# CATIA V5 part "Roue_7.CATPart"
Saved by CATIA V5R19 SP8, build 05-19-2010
Part number: Roue_7
Nomenclature: 70_R7
Bounding box of the stored display mesh (mm): x -12.994 to 12.994, y -13 to 13, z 0 to 1.5
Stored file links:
  C:\Users\rphgr\Desktop\0_Tapis_TC520B_vitesse\Roue_7.CATPart
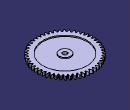
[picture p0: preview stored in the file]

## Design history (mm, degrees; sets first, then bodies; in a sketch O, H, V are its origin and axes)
External parameters (linked from other documents)
  External.Module = 0.5 mm
  External.Z = 50
  External.DiamPrimitif = 25 mm {= External.Module *External.Z}
  External.AnglePression = 20 deg
  External.x = 0
  External.DeportDenture = 0 mm {= External.x *External.Module}
  External.DiamBase = 23.4923 mm {= External.DiamPrimitif *cos(External.AnglePression )}
  External.DiamPied = 23.75 mm {= External.DiamPrimitif -2.5*External.Module +2*External.DeportDenture}
  External.DiamTete = 26 mm {= External.DiamPrimitif +2*External.Module +2*External.DeportDenture}
  External.PhiPrimitif = 0.854 deg {= atan((sin(External.ThetaPrimitif*1rad)-External.ThetaPrimitif*cos(External.ThetaPrimitif*1rad))/(cos(External.ThetaPrimitif*1rad)+External.ThetaPrimitif*sin(External.ThetaPrimitif*1rad)))}
  External.PhiTete = 1.7996 deg {= atan((sin(External.ThetaTete*1rad)-External.ThetaTete*cos(External.ThetaTete*1rad))/(cos(External.ThetaTete*1rad)+External.ThetaTete*sin(External.ThetaTete*1rad)))}
  External.PhiSymetrie = 1.8 deg {= 180*1 deg/(2*External.Z )}
  External.CongePied = 0.19 mm {= 0.38*External.Module}
  External.AlphaCopie = 7.2 deg {= 360*1 deg/External.Z}
  External.AlphaSymetrieCopie = 3.6 deg {= External.AlphaCopie /2}
  External.CoeffQualiteEngrenage = 7
  External.LargeurDenture = 1.5 mm
  External.ThetaPrimitif = 0.36397 {= sqrt(abs((External.DiamPrimitif*External.DiamPrimitif)/(External.DiamBase *External.DiamBase )-1))}
  External.ThetaTete = 0.47422 {= sqrt(abs((External.DiamTete*External.DiamTete)/(External.DiamBase *External.DiamBase )-1) )}
  External.Di = 24.2462 mm {= (External.DiamBase +External.DiamPrimitif )/2}
  External.Thetai = 0.255358 {= sqrt(abs((External.Di*External.Di)/(External.DiamBase*External.DiamBase)-1))}
  External.Phii = 0.3061 deg {= atan((sin(External.Thetai*1rad)-External.Thetai*cos(External.Thetai*1rad))/(cos(External.Thetai*1rad)+External.Thetai*sin(External.Thetai*1rad)))}
  External.Dj = 25.5 mm {= (External.DiamTete+External.DiamPrimitif)/2}
  External.Thetaj = 0.422169 {= sqrt(abs((External.Dj*External.Dj)/(External.DiamBase*External.DiamBase)-1))}
  External.Phij = 1.3005 deg {= atan((sin(External.Thetaj*1rad)-External.Thetaj*cos(External.Thetaj*1rad))/(cos(External.Thetaj*1rad)+External.Thetaj*sin(External.Thetaj*1rad)))}
  External.Dk = 23.8692 mm {= (External.Di+External.DiamBase)/2}
  External.Thetak = 0.179851 {= sqrt(abs((External.Dk*External.Dk)/(External.DiamBase*External.DiamBase)-1))}
  External.Phik = 0.109 deg {= atan((sin(External.Thetak*1rad)-External.Thetak*cos(External.Thetak*1rad))/(cos(External.Thetak*1rad)+External.Thetak*sin(External.Thetak*1rad)))}
  External.Dl = 24.6231 mm {= (External.DiamPrimitif+External.Di)/2}
  External.Thetal = 0.31398 {= sqrt(abs((External.Dl*External.Dl)/(External.DiamBase*External.DiamBase)-1))}
  External.Phil = 0.5585 deg {= atan((sin(External.Thetal*1rad)-External.Thetal*cos(External.Thetal*1rad))/(cos(External.Thetal*1rad)+External.Thetal*sin(External.Thetal*1rad)))}
  External.Dm = 25.25 mm {= (External.Dj+External.DiamPrimitif)/2}
  External.Thetam = 0.394001 {= sqrt(abs((External.Dm*External.Dm)/(External.DiamBase*External.DiamBase)-1))}
  External.Phim = 1.0701 deg {= atan((sin(External.Thetam*1rad)-External.Thetam*cos(External.Thetam*1rad))/(cos(External.Thetam*1rad)+External.Thetam*sin(External.Thetam*1rad)))}
  External.Dn = 25.75 mm {= (External.DiamTete+External.Dj)/2}
  External.Thetan = 0.448823 {= sqrt(abs((External.Dn*External.Dn)/(External.DiamBase*External.DiamBase)-1))}
  External.Phin = 1.544 deg {= atan((sin(External.Thetan*1rad)-External.Thetan*cos(External.Thetan*1rad))/(cos(External.Thetan*1rad)+External.Thetan*sin(External.Thetan*1rad)))}
  External.DiametreAlesage = 2 mm
Body1 (main body)
  Sketch1 on xy-plane, origin (0, 0, 0), H (1, 0, 0), V (0, 1, 0)
    construction circle A1 centre (0, 0) radius 12.5
    construction circle A2 centre (0, 0) radius 11.7462
    construction circle A3 centre (0, 0) radius 11.875
    construction circle A4 centre (0, 0) radius 13
    point P1 (11.7462, 0)
    construction line L1 (11.7462, 0) -> (0, 0)
    point P2 (12.4986, 0.1863)
    construction line L2 (12.4986, 0.1863) -> (0, 0)
    point P3 (12.9936, 0.4082)
    construction line L3 (12.9936, 0.4082) -> (0, 0)
    construction line L4 (11.7462, 0) -> (11.7462, 3.9367)
    point P4 (11.7462, 0)
    point P6 (10.9937, 0.1863)
    construction line L5 (12.9936, 0.4082) -> (12.4986, 0.1863)
    point P7 (12.7461, 0.2973)
    point P8 (10.7462, 0.2973)
    spline S1 through (10.7462, 0.2973) (10.9937, 0.1863) (11.7462, 0) (11.9346, 0.0227) (12.1229, 0.0648) (12.311, 0.12) (12.4986, 0.1863) (12.6228, 0.2358) (12.7467, 0.2894) (12.8703, 0.3469) (12.9936, 0.4082)
    construction line L6 (0, 0) -> (5.2687, 0.2442)
    spline S2 through (10.7276, 0.6981) (10.9638, 0.8315) (11.6958, 1.0866) (11.8855, 1.0814) (12.0769, 1.057) (12.2693, 1.0194) (12.4623, 0.9707) (12.5905, 0.9329) (12.7188, 0.891) (12.8472, 0.8452) (12.9756, 0.7955)
    arc A5 centre (12.0641, -0.1449) radius 0.19 from (12.0229, 0.0405) to (11.8741, -0.1427) ccw
    point P11 (11.8741, -0.1427)
    arc A6 centre (0, 0) radius 13 from (12.9936, 0.4082) to (12.9756, 0.7955) ccw
    point P13 (12.9756, 0.7955)
    arc A7 centre (11.999, 1.2603) radius 0.19 from (11.81, 1.2405) to (11.9751, 1.0719) ccw
    point P15 (11.81, 1.2405)
    construction line L7 (0, 0) -> (4.2577, 0.4666)
    construction line L8 (0, 0) -> (5.1252, -0.0846)
    point P19 (11.8043, 1.2936)
    arc A8 centre (0, 0) radius 11.875 from (11.81, 1.2405) to (11.8043, 1.2936) ccw
    point P20 (11.8734, -0.1961)
    arc A9 centre (0, 0) radius 11.875 from (11.8734, -0.1961) to (11.8741, -0.1427) ccw
    line L9 (11.8043, 1.2936) -> (0, 0)
    line L10 (11.8734, -0.1961) -> (0, 0)
    construction circle A10 centre (0, 0) radius 12.1231
    construction line L11 (0, 0) -> (2.5698, 0.0137)
    point P22 (12.1229, 0.0648)
    construction circle A11 centre (0, 0) radius 12.75
    construction line L12 (0, 0) -> (4.018, 0.0912)
    point P24 (12.7467, 0.2894)
    point P25 (12.7467, 0.2894)
    point P26 (12.7188, 0.891)
    point P27 (12.0769, 1.057)
    construction circle A12 centre (0, 0) radius 11.9346
    construction line L13 (0, 0) -> (48.2618, 0.0918)
    point P29 (11.8855, 1.0814)
    construction line L14 (0, 0) -> (63.9099, 2.9624)
    point P31 (11.9346, 0.0227)
    construction circle A13 centre (0, 0) radius 12.3115
    construction line L15 (0, 0) -> (57.3607, 0.5591)
    point P33 (12.311, 0.12)
    point P34 (12.2693, 1.0194)
    construction circle A14 centre (0, 0) radius 12.625
    construction line L16 (0, 0) -> (65.6993, 1.2272)
    point P36 (12.6228, 0.2358)
    point P37 (12.5905, 0.9329)
    construction circle A15 centre (0, 0) radius 12.875
    axis line L17 (0, 0) -> (59.3294, 1.5992)
    point P39 (12.8472, 0.8452)
    point P40 (12.8703, 0.3469)
    point P42 (10.7462, 0.2973)
    point P43 (10.9937, 0.1863)
    point P44 (11.7462, 0)
    point P45 (12.4986, 0.1863)
    point P46 (12.9936, 0.4082)
    point P47 (12.9756, 0.7955)
    point P48 (10.7276, 0.6981)
    point P49 (12.4623, 0.9707)
    point P50 (11.6958, 1.0866)
    point P51 (10.9638, 0.8315)
    point P52 (12.1229, 0.0648)
    point P53 (12.7467, 0.2894)
    point P54 (12.0769, 1.057)
    point P55 (12.7188, 0.891)
    point P56 (11.9346, 0.0227)
    point P57 (11.8855, 1.0814)
    point P58 (12.311, 0.12)
    point P59 (12.2693, 1.0194)
    point P60 (12.6228, 0.2358)
    point P61 (12.5905, 0.9329)
    point P62 (12.8703, 0.3469)
    point P63 (12.8472, 0.8452)
    radius A1 = 12.5 {= External.DiamPrimitif /2}
    radius A2 = 11.7462 {= External.DiamBase /2}
    radius A3 = 11.875 {= External.DiamPied /2}
    radius A4 = 13 {= External.DiamTete /2}
    angle L2 L1 = 0.854 {= External.PhiPrimitif}
    angle L3 L1 = 1.7996 {= External.PhiTete}
    angle L4 L1 = 90
    radius A5 = 0.19 {= External.CongePied}
    radius A7 = 0.19 {= External.CongePied}
    angle L7 L6 = 3.6 {= External.AlphaSymetrieCopie}
    angle L2 L6 = 1.8 {= External.PhiSymetrie}
    radius A10 = 12.1231 {= External.Di /2}
    angle L11 L1 = 0.3061 {= External.Phii}
    radius A11 = 12.75 {= External.Dj /2}
    angle L12 L1 = 1.3005 {= External.Phij}
    radius A12 = 11.9346 {= External.Dk/2}
    angle L13 L1 = 0.109 {= External.Phik}
    angle L14 L2 = 1.8 {= External.PhiSymetrie}
    radius A13 = 12.3115 {= External.Dl /2}
    angle L15 L1 = 0.5585 {= External.Phil}
    radius A14 = 12.625 {= External.Dm /2}
    angle L16 L1 = 1.0701 {= External.Phim}
    radius A15 = 12.875 {= External.Dn/2}
    angle L17 L1 = 1.544 {= External.Phin}
    coincidence: P1 A2, P1 H, P2 A1, P3 A4, P4 A2, P7 L5, P42 P8, P43 P6, P44 P1, P45 L5, P45 L2, P46 L5, P46 L3, P11 A3, P47 P13, P15 A3, P19 L7, P19 A3, P20 L8, P20 A3, P3 P46, P22 L11, P22 A10, P52 P22, P24 L12, P24 A11, P53 P24, P25 P53, P54 P27, P55 P26, P31 L13, P31 A12, P56 P31, P57 P29, P33 L15, P33 A13, P58 P33, P59 P34, P36 L16, P36 A14, P60 P36, P61 P37, P40 L17, P40 A15, P62 P40, P63 P39, O L9, O L10
    horizontal: L1 H
    tangency: L4 A2, A5 A3, A5 S1, A7 A3, A7 S2, A8 A5, A9 A5
    symmetry: P6 P2 L4, P8 P7 L4, P46 P47 L6, P42 P48 L6, P45 P49 L6, P44 P50 L6, P43 P51 L6, L8 L7 L6, P26 P25 L6, P27 P22 L6, P29 P31 L14, P34 P33 L14, P37 P36 L14, P39 P40 L14
    midpoint: P7 L5
    parallelism: L9 L7, L10 L8
    concentricity: A10 A2, A11 A1
  Pad1: profile Sketch1, direction (0, 0, 1), length 1.5 {= External.LargeurDenture}
  CircPattern1 "Roue Dentée": of Pad1, instances 50 {= External.Z}, angular step 7.2 {= External.AlphaCopie}, axis from Z axis
  Body2
    Sketch2 on xy-plane, origin (0, 0, 0), H (1, 0, 0), V (0, 1, 0)
      circle A1 centre (0, 0) radius 1
      radius A1 = 1 {= External.DiametreAlesage /2}
    Pad2: profile Sketch2, direction (0, 0, 1), length 3 {= 2*External.LargeurDenture}
  Remove1: tool Body2
  Sketch3 on face of CircPattern1, origin (0, 0, 1.5), H (1, 0, 0), V (0, -1, 0)
    circle A1 centre (0, 0) radius 2.5
    circle A2 centre (0, 0) radius 10
    radius A2 = 10
    radius A1 = 2.5
  Pocket1: profile Sketch3, direction (0, 0, -1), length 0.5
